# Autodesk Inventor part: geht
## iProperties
Shininess: 64.0
Length Units: 11269
Angle Units: 11279
Time Units: 11290
Mass Units: 11283
Length Display Precision: 3
Angle Display Precision: 2
Compacted: True
Part Number: geht
Document SubType Name: Modeling
Created: 2004-02
Material: Aluminium - 6061
Designer: oelmann
Manufacturer: Standard
Standards Organization: Custom
Description: Berechnung Füllung Kokille
Density: 0.0
Volumn: 0.0
Area: 0.0
PropertySet Name: Model Information
Control State: 0
Master: False
Checked Out: False
AIMD_DESCRIPTION: 600x1150
AIMD_ORIGIN: ENG-001076
ZNr: 20-KOK-130-1590
Author: oelmann
Title: Berechnung Füllung Kokille
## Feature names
1. Erhebung2
2. Trennen2
3. Erhebung4
